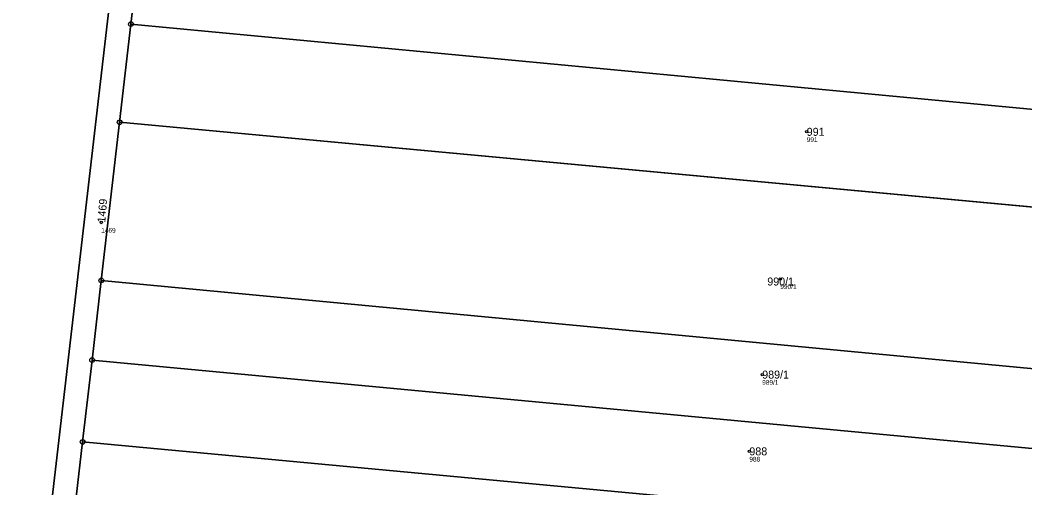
# Model space of a CAD drawing. Extents: x -658203 to -653176, y -1156738 to -1151709.
# Drawn here: x -655212.3 to -654998.7, y -1154007.6 to -1153908.2 of the extents above; entities that cross this region are included whole.
import ezdxf

# ---------------------------------------------------------------- set-up
doc = ezdxf.new("R2010")
doc.units = 0
for name, color, linetype in [('Vrstva 1', 7, 'Continuous'), ('Vrstva 2', 7, 'Continuous'), ('Vrstva 50', 7, 'Continuous'), ('Vrstva 51', 7, 'Continuous'), ('Vrstva 8', 7, 'Continuous')]:
    doc.layers.add(name, color=color, linetype=linetype)

msp = doc.modelspace()

# ---------------------------------------------------------------- linework, layer by layer
at = {"layer": 'Vrstva 1'}
for p, q in [((-655188.71, -1153909.09), (-655184.85, -1153875.72)), ((-655191.12, -1153929.95), (-655188.71, -1153909.09)), ((-654909.87, -1153935.44), (-655188.71, -1153909.09)), ((-655195, -1153963.52), (-655191.12, -1153929.95)), ((-655191.12, -1153929.95), (-654913.72, -1153955.69)), ((-655195, -1153963.52), (-655196.96, -1153980.46)), ((-654993.01, -1153982.68), (-655195, -1153963.52)), ((-655198.97, -1153997.84), (-655196.96, -1153980.46)), ((-655196.96, -1153980.46), (-654923.33, -1154006.15)), ((-655200.32, -1154009.56), (-655198.97, -1153997.84)), ((-654926.58, -1154023.25), (-655198.97, -1153997.84))]:
    msp.add_line(p, q, dxfattribs=at)
msp.add_lwpolyline([(-655170.28, -1153706.06), (-655190.35, -1153879.69), (-655216.4, -1154104.29)], dxfattribs=at)
at = {"layer": 'Vrstva 50'}
for centre in [(-655045.11, -1153931.97), (-655195.02, -1153951.23), (-655050.72, -1153963.2), (-655054.57, -1153983.54), (-655057.3, -1153999.85)]:
    msp.add_circle(centre, 0.25, dxfattribs=at)
at = {"layer": 'Vrstva 51'}
for points in [[(-655278.37, -1154072.63), (-655273.64, -1154075.39), (-655243.01, -1154090.64), (-655216.4, -1154104.29), (-655190.35, -1153879.69), (-655170.28, -1153706.06), (-655234.51, -1153699.93)], [(-655184.85, -1153875.72), (-655188.71, -1153909.09), (-654909.87, -1153935.44), (-654903.59, -1153902.42), (-654979.99, -1153895.17)], [(-655191.12, -1153929.95), (-654913.72, -1153955.69), (-654909.87, -1153935.44), (-655188.71, -1153909.09)], [(-654942.35, -1153957.05), (-654914.47, -1153959.64), (-654913.72, -1153955.69), (-655191.12, -1153929.95), (-655195, -1153963.52), (-654993.01, -1153982.68), (-654990.14, -1153952.62), (-654966.25, -1153954.84)], [(-654993.01, -1153982.68), (-655195, -1153963.52), (-655196.96, -1153980.46), (-654923.33, -1154006.15), (-654920.18, -1153989.59), (-654945.16, -1153987.22), (-654969.06, -1153984.95)], [(-654926.58, -1154023.25), (-654923.33, -1154006.15), (-655196.96, -1153980.46), (-655198.97, -1153997.84)], [(-655200.32, -1154009.56), (-654928.73, -1154034.88), (-654926.58, -1154023.25), (-655198.97, -1153997.84)]]:
    msp.add_lwpolyline(points, close=True, dxfattribs=at)
msp.add_lwpolyline([(-655190.35, -1153879.69), (-655216.4, -1154104.29), (-655211.54, -1154106.65), (-655205.91, -1154057.93), (-655205.68, -1154055.94), (-655205.03, -1154050.33), (-655204.07, -1154042.03), (-655201.89, -1154023.11), (-655200.32, -1154009.56), (-655198.97, -1153997.84), (-655196.96, -1153980.46), (-655195, -1153963.52), (-655191.12, -1153929.95), (-655188.71, -1153909.09), (-655184.85, -1153875.72)], dxfattribs=at)
at = {"layer": 'Vrstva 8'}
for centre, radius in [((-655188.71, -1153909.09), 0.5), ((-655188.71, -1153909.09), 0.0303), ((-655191.12, -1153929.95), 0.5), ((-655191.12, -1153929.95), 0.0303), ((-655195, -1153963.52), 0.5), ((-655195, -1153963.52), 0.0303), ((-655196.96, -1153980.46), 0.5), ((-655196.96, -1153980.46), 0.0303), ((-655198.97, -1153997.84), 0.5), ((-655198.97, -1153997.84), 0.0303)]:
    msp.add_circle(centre, radius, dxfattribs=at)

# ---------------------------------------------------------------- texts
at = {"layer": 'Vrstva 2'}
for s, p in [('991', (-655045.11, -1153932.82)), ('990/1', (-655053.49, -1153964.62)), ('989/1', (-655054.57, -1153984.39)), ('988', (-655057.3, -1154000.7))]:
    msp.add_text(s, height=1.7, dxfattribs=at).set_placement(p)
msp.add_text('1469', height=1.7, rotation=85, dxfattribs=at).set_placement((-655194.17, -1153951.3))
at = {"layer": 'Vrstva 50'}
for s, p in [('991', (-655045.11, -1153934.13)), ('1469', (-655195.02, -1153953.39)), ('990/1', (-655050.72, -1153965.36)), ('989/1', (-655054.57, -1153985.7)), ('988', (-655057.3, -1154002.01))]:
    msp.add_text(s, height=1, dxfattribs=at).set_placement(p)

doc.saveas('drawing.dxf')
